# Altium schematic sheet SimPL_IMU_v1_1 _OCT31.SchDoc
size 299 x 236 mm
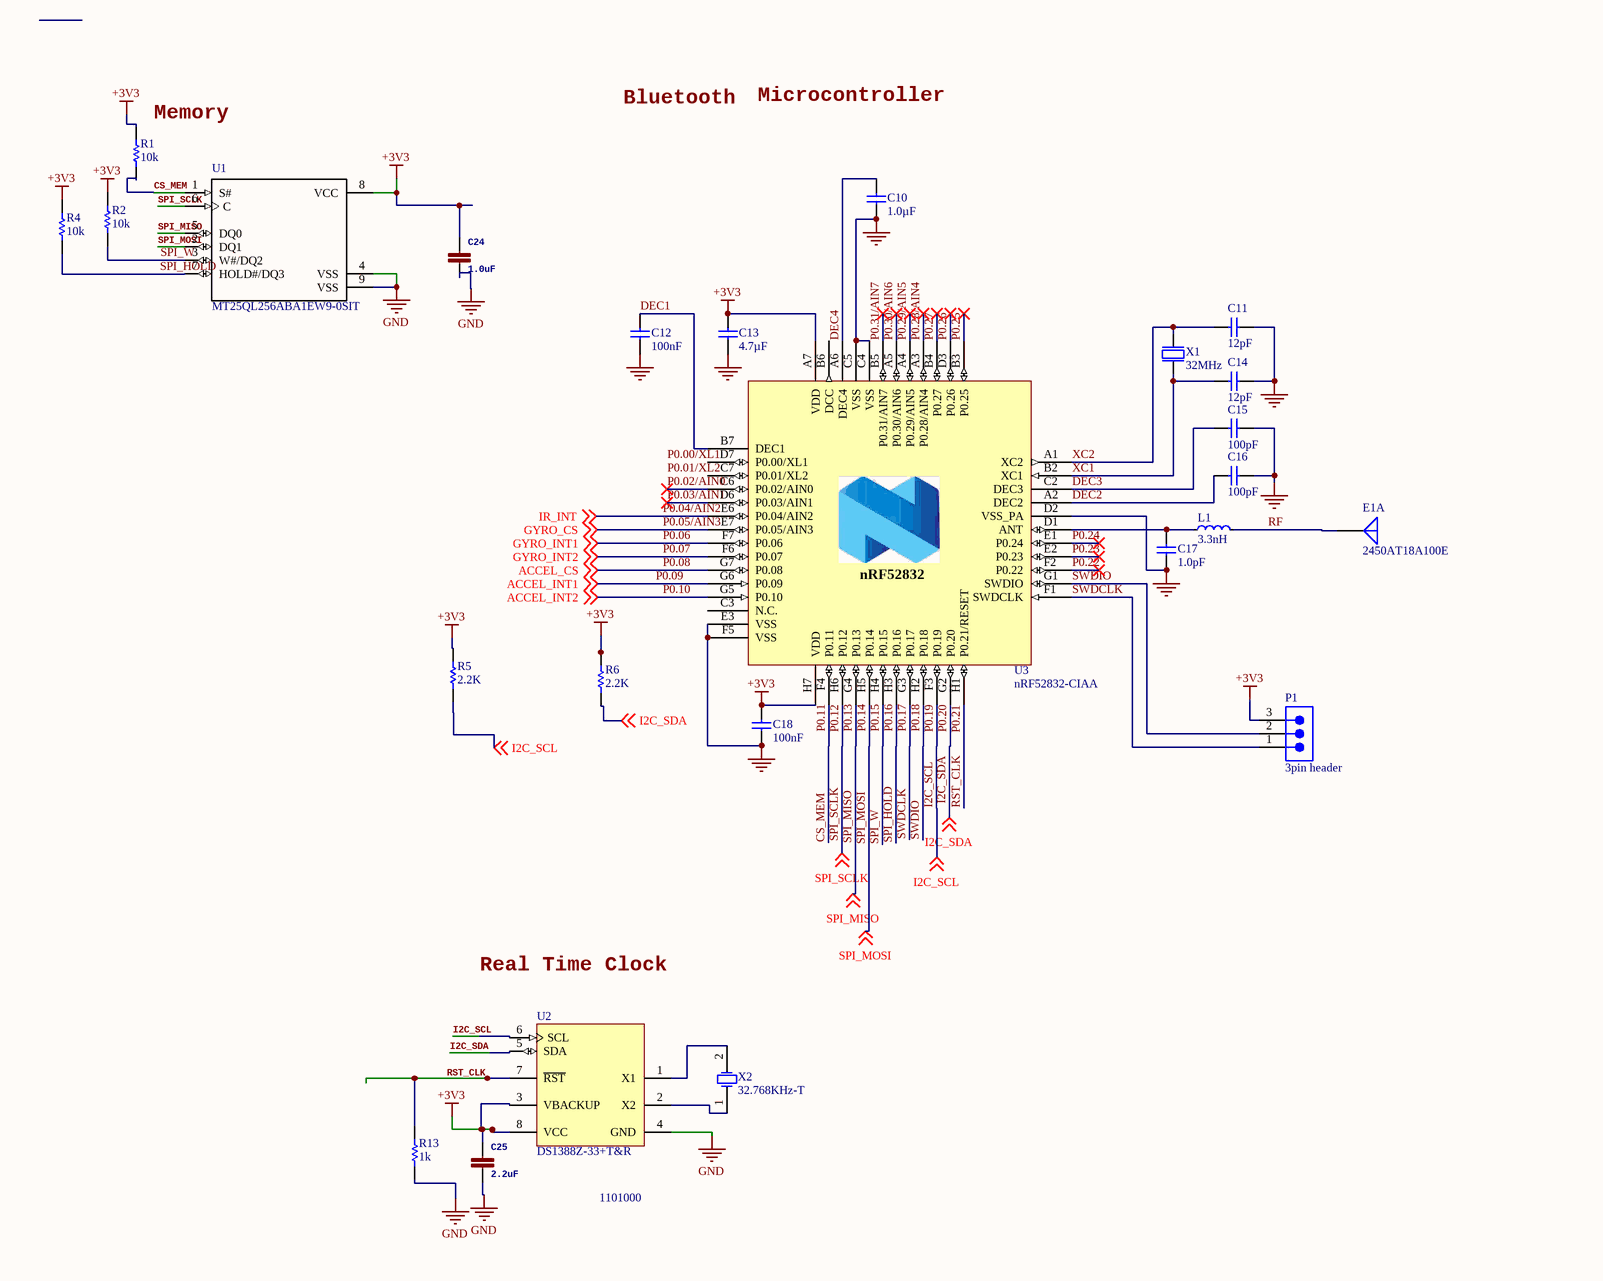
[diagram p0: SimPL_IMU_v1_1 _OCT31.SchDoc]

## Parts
C10  1.0µF  [CAPC1005X04L]
C11  12pF  [CAPC0603X03L]
C12  100nF  [CAPC0603X03L]
C13  4.7µF  [CAPC1608X06L]
C14  12pF  [CAPC0603X03L]
C15  100pF  [CAPC0603X03L]
C16  100pF  [CAPC0603X03L]
C17  1.0pF  [CAPC0603X03L]
C18  100nF  [CAPC0603X03L]
C24  1.0uF  [0402]
C25  2.2uF  [0402]
E1  2450AT18A100E  [JT-2450AT18A100-2_V]  (part A of 2)
L1  3.3nH  [INDC0603X03L]
P1  3pin header  [SMTC-TSW-103-07-X-S]
R1  10k  [RESC1005X40X25NL05T05]
R2  10k  [RESC1005X40X25NL05T05]
R4  10k  [RESC1005X40X25NL05T05]
R5  2.2K  [RESC1005X40X25ML10T10]
R6  2.2K  [RESC1005X40X25ML10T10]
R13  1k  [RESC1005X40X25NL05T05]
U1  MT25QL256ABA1EW9-0SIT  [*SON127P600X800X80-9N]
U2  DS1388Z-33+T&R  [S8+4_M]
U3  nRF52832-CIAA  [BGA50C40P7X8_295X322X50]
X1  32MHz  [BT-XTAL_2016]
X2  32.768KHz-T  [ABRA-ABS07-2_V]

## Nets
+3V3: C13.1 C18.1 C24.1 C25.1 P1.3 R1.2 R2.2 R4.2 R5.2 R6.2 U1.8(VCC) U2.3(VBACKUP) U2.8(VCC) U3.A7(VDD) U3.H7(VDD)
GND: C10.1 C11.1 C12.2 C13.2 C14.1 C15.2 C16.1 C17.1 C18.2 C24.2 C25.2 R13.1 U1.4(VSS) U1.9(VSS) U2.4(GND) U3.C4(VSS) U3.C5(VSS) U3.D2(VSS_PA) U3.E3(VSS) U3.F5(VSS) X1.2(GND) X1.4(GND)
CS_MEM: R1.1 U1.1(S#) U3.F4(P0.11)  [also labelled P0.11]
DEC1: C12.1 U3.B7(DEC1)
DEC2: C16.2 U3.A2(DEC2)
DEC3: C15.1 U3.C2(DEC3)
DEC4: C10.2 U3.A6(DEC4)
I2C_SCL: R5.1 U2.6(SCL) U3.F3(P0.19) ; off-sheet I2C_SCL  [also labelled P0.19]
I2C_SDA: R6.1 U2.5(SDA) U3.G2(P0.20) ; off-sheet I2C_SDA  [also labelled P0.20]
P0.02/AIN0: U3.C6(P0.02/AIN0)
P0.03/AIN1: U3.D6(P0.03/AIN1)
P0.04/AIN2: U3.E6(P0.04/AIN2) ; off-sheet IR_INT  [also labelled IR_INT]
P0.05/AIN3: U3.E7(P0.05/AIN3) ; off-sheet GYRO_CS  [also labelled GYRO_CS]
P0.06: U3.F7(P0.06) ; off-sheet GYRO_INT1  [also labelled GYRO_INT1]
P0.07: U3.F6(P0.07) ; off-sheet GYRO_INT2  [also labelled GYRO_INT2]
P0.08: U3.G7(P0.08) ; off-sheet ACCEL_CS  [also labelled ACCEL_CS]
P0.09: U3.G6(P0.09) ; off-sheet ACCEL_INT1  [also labelled ACCEL_INT1]
P0.10: U3.G5(P0.10) ; off-sheet ACCEL_INT2  [also labelled ACCEL_INT2]
P0.12: U1.6(C) U3.H6(P0.12) ; off-sheet SPI_SCLK  [also labelled SPI_SCLK]
P0.13: U1.5(DQ0) U3.G4(P0.13) ; off-sheet SPI_MISO  [also labelled SPI_MISO]
P0.14: U1.2(DQ1) U3.H5(P0.14) ; off-sheet SPI_MOSI  [also labelled SPI_MOSI]
P0.15: R2.1 U1.3(W#/DQ2) U3.H4(P0.15)  [also labelled SPI_W]
P0.16: R4.1 U1.7(HOLD#/DQ3) U3.H3(P0.16)  [also labelled SPI_HOLD]
P0.17: P1.1 U3.F1(SWDCLK) U3.G3(P0.17)  [also labelled SWDCLK]
P0.18: P1.2 U3.G1(SWDIO) U3.H2(P0.18)  [also labelled SWDIO]
P0.21: U3.H1(P0.21/RESET)  [also labelled RST_CLK]
P0.22: U3.F2(P0.22)
P0.23: U3.E2(P0.23)
P0.24: U3.E1(P0.24)
P0.25: U3.B3(P0.25)
P0.26: U3.D3(P0.26)
P0.27: U3.B4(P0.27)
P0.28/AIN4: U3.A3(P0.28/AIN4)
P0.29/AIN5: U3.A4(P0.29/AIN5)
P0.30/AIN6: U3.A5(P0.30/AIN6)
P0.31/AIN7: U3.B5(P0.31/AIN7)
RF: E1.1(FP) L1.2
XC1: C14.2 U3.B2(XC1) X1.1(inp)
XC2: C11.2 U3.A1(XC2) X1.3(out)
NetC17_2: C17.2 L1.1 U3.D1(ANT)
NetR13_2: R13.2 U2.7(~{RST})
NetU2_1: U2.1(X1) X2.2(X2)
NetU2_2: U2.2(X2) X2.1(X2)

Not connected (* = marked no-connect by the designer): U3 B6(DCC) C3(N.C.) C7(P0.01/XL2) D7(P0.00/XL1)

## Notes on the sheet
- (near R1) Memory
- Bluetooth
- Microcontroller
- Real Time Clock
- 1101000
- Labels drawn without touching a wire or pin: P0.00/XL1, P0.01/XL2, RST_CLK

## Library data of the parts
C10 = C0402-1µ0: Capacitor, X5R, ±5%; Note: 6.3V; Artikkelnr Noca: 20039235; Artikkelnr Simpro: N.A.
C11 C14 = C0201-12p: Capacitor, NP0, ±2%; Note: 50V; Artikkelnr Noca: N.A.
C12 C18 = C0201-100n: Capacitor, X7R, ±10%; Note: 16V; Artikkelnr Noca: N.A.
C13 = C0603-4µ7: Capacitor, X5R, ±10%; Note: 6.3V; Artikkelnr Noca: 20069060; Artikkelnr Simpro: N.A.
C15 C16 = C0201-100p: Capacitor, NP0, ±5%; Note: Chip Cap 1%; Artikkelnr Noca: N.A.
C17 = C0201-1.0p: Capacitor, NP0, ±5%; Note: Chip Cap 1%; Artikkelnr Noca: N.A.
C24 = 1.0UF-0402-16V-10%: 1?¦ÌF ceramic capacitors    A capacitor is a passive two-terminal electrical component used to store electrical energy temporarily in an electric field.; GateName_1: G$1; SymbolName_1: CAP; PROD_ID: CAP-12417
C25 = 0.1UF-0402-16V-10%: 0.1ÂµF ceramic capacitors    A capacitor is a passive two-terminal electrical component used to store electrical energy temporarily in an electric field.; GateName_1: G$1; SymbolName_1: CAP; DeviceSetName: 0.1UF; PROD_ID: CAP-12416
E1 = CMP-2000-05167-1: Ceramic Antenna, 2.45 GHZ, 2 W, -40 to 125 degC, 2-Pin SMD, RoHS, Tape and Reel; Manufacturer: Johanson Technology; Maximum Frequency: 2500MHz; Typical Antenna Gain: 0.5dB; Minimum Frequency: 2400MHz
L1 = L0201-3n3: High frequency chip inductor ±5%; Artikkelnr Noca: N.A.
P1 = CMP-1024-00331-1: 0.025" SQ Post Header, Through-hole, Vertical, -55 to 125 degC, 2.54 mm Pitch, 3-Pin, Male, RoHS; Manufacturer: Samtec; PartNumber: TSW-103-07-F-S; Pitch: 2.54 mm
R1 R2 R4 = CMP-2002-00607-3: Chip Resistor, 10 KOhm, +/- 1%, 100 mW, -55 to 155 degC, 0402 (1005 Metric), RoHS, Tape and Reel; Manufacturer: Basic Passives; PartNumber: ERJ-2RKF1002X; Case\/Package: 0402; Resistance: 10 KOhm; Voltage Rating: 50 V; Power Rating: 100 mW
R5 R6 = CMP-2002-06097-1: Part Number: MC00625W040212K2; Manufacturer: Multicomp
R13 = CMP-2002-08276-1: Manufacturer: Vishay Dale; Part Number: CRCW04021K00FKED
U1 = MT25QL256ABA1EW9-0SIT: NOR Flash Serial-SPI 3.3V 256Mbit 256M x 1bit 8-Pin WPDFN; MF: Micron Technology
U2 = CMP-0254-00385-1: I2C Real-Time Clock/Supervisor with Trickle Charger and 512 Byte EEPROM, 3.3V, 8-Pin SO, -40 to 85 degC, Pb-Free, Reel
U3 = nRF52832-CIAA: Multi-protocol Bluetooth Low Energy, ANT and 2.4GHz proprietary system-on-chip; Manufacturer: Nordic Semiconductor; Artikkelnr Noca: N.A.
X1 = XTAL_SMD2016_32MHz_8pF_Epson: XTAL SMD 2016, 32MHz, Cl=8pF, Total Tol: ±40ppm; Manufacturer: Epson Toyocom; Manufacturer Part Number: Q22FA12800025; Note: XTAL SMD 32.000MHz; Artikkelnr Noca: N.A.
X2 = CMP-0447-00001-2: Crystal, 32.768 kHz, 12.5 pF, -40 to 85 degC, SMD Low Profile 3.2 x 1.5 x 0.9 mm, Tape and Reel; Manufacturer: Abracon; PartNumber: ABS07-32.768KHz-T; Q Value (Type): 30000; Operation Mode: Flexural Mode (Tuning Fork); Shunt Capacitance (C0): 0.9 to 1.2 pF; Load Capacitance (CL): 12.5 pF; Frequency Tolerance @+25degC: +/- 20 ppm; Drive Level (Type): 0.1 uW; Equivalent Series Resistance (R1): 70 Kohm; Insulation Resistance (Min): 500 Mohm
